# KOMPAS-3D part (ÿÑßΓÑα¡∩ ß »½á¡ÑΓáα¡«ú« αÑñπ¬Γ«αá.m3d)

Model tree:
1. Эскиз:1
2. Операция выдавливания:1
     Расстояние 1 = 5; Расстояние 2 = 5
3. Фаска:1
     Угол = 45; Длина 1 = 0.5; Длина 2 = 0.5
